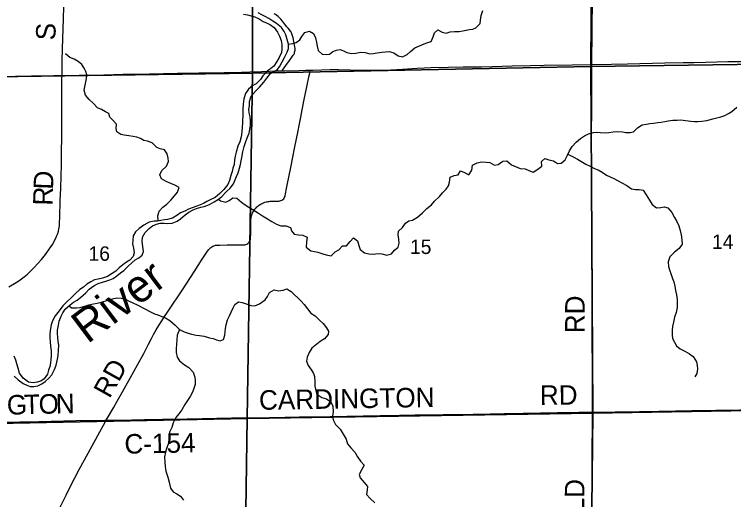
# Model space of a CAD drawing. Extents: x 1584893 to 1934202, y 663575 to 1091909.
# Drawn here: x 1821820 to 1832870, y 914623 to 922073 of the extents above; entities that cross this region are included whole.
import ezdxf

# ---------------------------------------------------------------- set-up
doc = ezdxf.new("R2010")
doc.units = 0
for name, color, linetype in [('GM_X_County_Road', 7, 'Continuous'), ('GM_X_County_Road_Text', 7, 'Continuous'), ('GM_X_Major_River', 7, 'Continuous'), ('GM_X_Major_River_Text', 7, 'Continuous'), ('GM_X_Minor_River', 7, 'Continuous'), ('GM_X_Section', 7, 'Continuous'), ('GM_X_Section_Text', 7, 'Continuous'), ('GM_X_Township_Road', 7, 'Continuous'), ('GM_X_Township_Road_Text', 7, 'Continuous')]:
    doc.layers.add(name, color=color, linetype=linetype)

msp = doc.modelspace()

# ---------------------------------------------------------------- linework, layer by layer
at = {"layer": 'GM_X_County_Road'}
for points in [[(1830693, 921304), (1830693, 921360), (1830695, 921787), (1830698, 921918), (1830701, 922230), (1830703, 922476), (1830705, 922739), (1830708, 923083), (1830710, 923346), (1830712, 923559), (1830715, 923838), (1830718, 924035), (1830719, 924220)], [(1822552, 921136), (1822553, 921203), (1822555, 921351), (1822560, 921548), (1822574, 922007), (1822578, 922188)], [(1830693, 921304), (1830994, 921310), (1831239, 921316), (1831813, 921328), (1832092, 921333), (1832256, 921336), (1832436, 921339), (1832780, 921348), (1832977, 921351), (1833256, 921358), (1833319, 921358)], [(1826362, 921217), (1826405, 921218), (1826667, 921225), (1826798, 921225), (1826978, 921221), (1827142, 921217), (1827323, 921214), (1827437, 921216), (1827601, 921223), (1827781, 921233), (1828010, 921248), (1828223, 921257), (1828485, 921265), (1828715, 921268), (1828994, 921270), (1829158, 921275), (1829469, 921282), (1829748, 921286), (1829961, 921291), (1830387, 921298), (1830682, 921304), (1830693, 921304)], [(1830703, 915967), (1830703, 916109), (1830702, 916322), (1830699, 916700), (1830698, 917028), (1830698, 917159), (1830697, 917373), (1830695, 917816), (1830695, 918013), (1830693, 918292), (1830690, 918833), (1830689, 919211), (1830687, 919473), (1830687, 919769), (1830687, 920277), (1830689, 920589), (1830689, 920819), (1830691, 920999), (1830693, 921304)], [(1818576, 921109), (1818621, 921108), (1818736, 921107), (1818917, 921106), (1819409, 921104), (1819852, 921102), (1820048, 921105), (1820163, 921105), (1820426, 921107), (1820602, 921108), (1820770, 921110), (1820852, 921112), (1821082, 921115), (1821459, 921120), (1821836, 921125), (1822082, 921128), (1822427, 921133), (1822552, 921136)], [(1821735, 917892), (1821849, 917957), (1821890, 917983), (1821931, 918011), (1821970, 918042), (1822020, 918085), (1822124, 918186), (1822180, 918246), (1822234, 918308), (1822296, 918385), (1822345, 918451), (1822382, 918505), (1822385, 918510), (1822408, 918547), (1822432, 918591), (1822454, 918635), (1822474, 918680), (1822485, 918711), (1822495, 918743), (1822503, 918775), (1822511, 918824), (1822515, 918873), (1822519, 918956), (1822525, 919218), (1822531, 919399), (1822538, 919595), (1822543, 919759), (1822546, 919956), (1822548, 920186), (1822548, 920383), (1822548, 920564), (1822549, 920662), (1822551, 920892), (1822551, 921089), (1822552, 921136)], [(1822552, 921136), (1822619, 921137), (1822815, 921139), (1823192, 921147), (1823487, 921154), (1823897, 921162), (1824110, 921166), (1824324, 921169), (1824651, 921176), (1825045, 921182), (1825307, 921188), (1825438, 921192), (1825618, 921198), (1825864, 921204), (1825929, 921205)], [(1823231, 915840), (1823261, 915892), (1823342, 916034), (1823398, 916134), (1823479, 916277), (1823657, 916590), (1823713, 916692), (1823806, 916865), (1823882, 917011), (1823926, 917099), (1823957, 917157), (1823997, 917227), (1824040, 917298), (1824084, 917367), (1824128, 917436), (1824183, 917517), (1824266, 917640), (1824320, 917722), (1824401, 917845), (1824580, 918120), (1824706, 918313), (1824788, 918436), (1824807, 918462), (1824817, 918474), (1824828, 918485), (1824840, 918496), (1824853, 918505), (1824867, 918513), (1824882, 918519), (1824897, 918524), (1824912, 918527), (1824928, 918530), (1824944, 918531), (1824977, 918532), (1825091, 918535), (1825206, 918536), (1825305, 918537), (1825349, 918536), (1825362, 918537), (1825375, 918540), (1825389, 918545), (1825404, 918554), (1825417, 918565), (1825427, 918578), (1825436, 918592), (1825441, 918606), (1825445, 918621), (1825448, 918638), (1825449, 918655), (1825450, 918676), (1825452, 918714), (1825452, 918751), (1825450, 918835), (1825450, 918884), (1825451, 918917), (1825452, 918933), (1825455, 918949), (1825458, 918965), (1825462, 918980), (1825467, 918996), (1825473, 919011), (1825480, 919025), (1825488, 919039), (1825496, 919053), (1825505, 919067), (1825514, 919080), (1825524, 919093), (1825535, 919105), (1825546, 919116), (1825558, 919127), (1825571, 919137), (1825584, 919147), (1825597, 919156), (1825611, 919164), (1825626, 919171), (1825640, 919178), (1825655, 919184), (1825670, 919189), (1825686, 919194), (1825702, 919197), (1825718, 919200), (1825734, 919202), (1825750, 919204), (1825782, 919205), (1825865, 919206), (1825881, 919207), (1825898, 919209), (1825914, 919214), (1825930, 919220), (1825946, 919230), (1825959, 919243), (1825967, 919256), (1825974, 919271), (1825979, 919288), (1825986, 919320), (1826002, 919401), (1826012, 919449), (1826066, 919723), (1826099, 919883), (1826125, 920012), (1826180, 920285), (1826196, 920365), (1826221, 920494), (1826243, 920607), (1826274, 920767), (1826315, 920960), (1826351, 921137), (1826357, 921169), (1826359, 921186), (1826362, 921217)], [(1825929, 921205), (1825979, 921206), (1826192, 921213), (1826290, 921216), (1826362, 921217)], [(1823231, 915840), (1823310, 915842), (1823424, 915843), (1823818, 915851), (1824096, 915856), (1824244, 915859), (1824473, 915864), (1824703, 915867), (1824932, 915872), (1825162, 915876), (1825441, 915880), (1825736, 915884), (1825982, 915890), (1826195, 915894), (1826670, 915901), (1827179, 915909), (1827441, 915913), (1827736, 915919), (1827769, 915920), (1827818, 915921), (1827974, 915923), (1828164, 915925), (1828304, 915926), (1828408, 915928), (1828588, 915931), (1828867, 915936), (1829129, 915941), (1829343, 915944), (1829638, 915950), (1830162, 915959), (1830490, 915963), (1830703, 915967)], [(1830640, 910601), (1830643, 910957), (1830649, 911269), (1830656, 911597), (1830661, 911843), (1830668, 912319), (1830674, 912598), (1830678, 912877), (1830684, 913188), (1830686, 913481), (1830687, 913631), (1830690, 913894), (1830694, 914255), (1830695, 914649), (1830695, 914829), (1830697, 915059), (1830698, 915453), (1830700, 915683), (1830703, 915967)], [(1830703, 915967), (1831048, 915971), (1831425, 915978), (1831720, 915983), (1832228, 915991), (1832966, 916002), (1833245, 916006), (1833318, 916007)], [(1821851, 913136), (1821871, 913176), (1821979, 913397), (1822095, 913634), (1822168, 913780), (1822260, 913973), (1822304, 914061), (1822411, 914281), (1822541, 914547), (1822614, 914693), (1822673, 914811), (1822748, 914956), (1822817, 915087), (1822895, 915231), (1823100, 915606), (1823220, 915820), (1823231, 915840)]]:
    msp.add_lwpolyline(points, dxfattribs=at)
at = {"layer": 'GM_X_Major_River'}
for points in [[(1823171, 917960), (1823227, 917978), (1823285, 917995), (1823339, 918018), (1823394, 918059), (1823449, 918107), (1823499, 918142), (1823570, 918207), (1823625, 918258), (1823675, 918302), (1823730, 918337), (1823782, 918378), (1823801, 918432), (1823783, 918588), (1823788, 918652), (1823827, 918722), (1823892, 918787), (1823943, 918826), (1824001, 918853), (1824057, 918865), (1824119, 918868), (1824177, 918863), (1824245, 918866), (1824320, 918899), (1824372, 918934), (1824445, 918993), (1824500, 919035), (1824566, 919074), (1824618, 919095), (1824685, 919112), (1824735, 919123), (1824815, 919152), (1824888, 919193), (1824954, 919236), (1825005, 919278), (1825072, 919349), (1825135, 919404), (1825186, 919471), (1825206, 919525), (1825233, 919585), (1825256, 919640), (1825279, 919710), (1825294, 919768), (1825305, 919822), (1825313, 919876), (1825329, 919964), (1825348, 920043), (1825371, 920107), (1825398, 920177), (1825425, 920250), (1825438, 920310), (1825448, 920368), (1825449, 920446), (1825440, 920498), (1825425, 920561), (1825422, 920615), (1825433, 920668), (1825433, 920733), (1825454, 920802), (1825487, 920854), (1825532, 920905), (1825583, 920955), (1825654, 921032), (1825696, 921093), (1825757, 921164), (1825810, 921198), (1825860, 921225), (1825897, 921278), (1825932, 921344), (1825969, 921411), (1826010, 921493), (1826031, 921547), (1826030, 921617), (1825988, 921757), (1825965, 921808), (1825921, 921872), (1825846, 921935), (1825791, 921968), (1825727, 922009), (1825674, 922040), (1825620, 922067), (1825563, 922095)], [(1825339, 922078), (1825401, 922064), (1825457, 922050), (1825513, 922034), (1825581, 922005), (1825643, 921965), (1825701, 921939), (1825757, 921915), (1825809, 921874), (1825862, 921802), (1825894, 921740), (1825918, 921670), (1825928, 921610), (1825929, 921544), (1825921, 921486), (1825889, 921412), (1825853, 921348), (1825806, 921278), (1825756, 921238), (1825706, 921207), (1825638, 921127), (1825601, 921071), (1825533, 921007), (1825483, 920979), (1825415, 920925), (1825370, 920858), (1825344, 920774), (1825334, 920696), (1825331, 920618), (1825331, 920556), (1825325, 920406), (1825320, 920336), (1825314, 920270), (1825302, 920192), (1825281, 920114), (1825255, 920050), (1825229, 919958), (1825213, 919894), (1825202, 919840), (1825194, 919768), (1825178, 919714), (1825164, 919660), (1825147, 919598), (1825123, 919522), (1825101, 919462), (1825036, 919386), (1824976, 919322), (1824906, 919263), (1824828, 919227), (1824778, 919201), (1824723, 919171), (1824673, 919149), (1824621, 919128), (1824549, 919102), (1824493, 919082), (1824439, 919054), (1824373, 919025), (1824318, 918987), (1824248, 918943), (1824174, 918923), (1824124, 918919), (1824072, 918908), (1824018, 918900), (1823966, 918898), (1823892, 918882), (1823809, 918839), (1823737, 918783), (1823679, 918735), (1823647, 918673), (1823638, 918603), (1823636, 918551), (1823648, 918481)], [(1823648, 918481), (1823660, 918413), (1823647, 918353), (1823591, 918299), (1823541, 918267), (1823487, 918230), (1823431, 918182), (1823376, 918130), (1823322, 918092), (1823252, 918048), (1823174, 918023), (1823106, 918009), (1823052, 917995), (1822992, 917969), (1822935, 917930), (1822881, 917884), (1822825, 917850), (1822753, 917784), (1822566, 917599), (1822507, 917523), (1822445, 917443), (1822405, 917367), (1822385, 917307), (1822372, 917249), (1822366, 917171), (1822366, 917107), (1822370, 917045), (1822377, 916979), (1822385, 916907), (1822387, 916831), (1822382, 916775), (1822372, 916721), (1822362, 916665), (1822346, 916609), (1822326, 916549), (1822279, 916477), (1822225, 916440), (1822171, 916424), (1822109, 916414), (1822037, 916428), (1821955, 916485), (1821897, 916563), (1821876, 916641), (1821856, 916709), (1821842, 916765), (1821814, 916823)], [(1821816, 916520), (1821879, 916461), (1821957, 916404), (1822010, 916378), (1822062, 916361), (1822118, 916360), (1822182, 916371), (1822239, 916398), (1822295, 916436), (1822348, 916487), (1822393, 916540), (1822436, 916618), (1822463, 916685), (1822484, 916779), (1822491, 916835), (1822498, 916915), (1822501, 916989), (1822494, 917053), (1822487, 917113), (1822481, 917173), (1822482, 917223), (1822497, 917303), (1822510, 917361), (1822537, 917439), (1822562, 917490), (1822601, 917546), (1822676, 917615), (1822730, 917654), (1822785, 917685), (1822841, 917729), (1822910, 917792), (1822971, 917855), (1823040, 917906), (1823108, 917939), (1823171, 917960)]]:
    msp.add_lwpolyline(points, dxfattribs=at)
at = {"layer": 'GM_X_Minor_River'}
for points in [[(1826030, 921617), (1826098, 921626), (1826150, 921641), (1826203, 921680), (1826235, 921732), (1826284, 921793), (1826355, 921816), (1826414, 921782), (1826445, 921715), (1826462, 921639), (1826473, 921583), (1826487, 921520), (1826548, 921464), (1826610, 921455), (1826660, 921464), (1826714, 921501), (1826769, 921523), (1826823, 921534), (1826874, 921513), (1826928, 921488), (1827000, 921473), (1827064, 921480), (1827138, 921491), (1827208, 921490), (1827282, 921467), (1827334, 921473), (1827392, 921482), (1827464, 921493), (1827520, 921500), (1827580, 921503), (1827650, 921484), (1827717, 921435), (1827785, 921422), (1827854, 921458), (1827906, 921505), (1827973, 921558), (1828042, 921591), (1828116, 921620), (1828170, 921639), (1828222, 921655), (1828253, 921726), (1828272, 921790), (1828325, 921837), (1828390, 921798), (1828452, 921785), (1828517, 921805), (1828581, 921810), (1828653, 921809), (1828711, 921818), (1828811, 921841), (1828861, 921848), (1828911, 921865), (1828974, 921932), (1828983, 921986), (1828990, 922054), (1829019, 922132)], [(1824030, 918902), (1824024, 918980), (1824044, 919050), (1824099, 919114), (1824163, 919159), (1824221, 919223), (1824282, 919289), (1824328, 919343), (1824350, 919413), (1824284, 919453), (1824222, 919477), (1824154, 919506), (1824082, 919548), (1824055, 919608), (1824087, 919674), (1824159, 919740), (1824188, 919814), (1824182, 919866), (1824168, 919932), (1824128, 919994), (1824058, 920010), (1824006, 920030), (1823938, 920099), (1823866, 920125), (1823807, 920139), (1823755, 920166), (1823703, 920190), (1823645, 920196), (1823579, 920206), (1823507, 920219), (1823455, 920229), (1823393, 920271), (1823385, 920321), (1823387, 920385), (1823339, 920443), (1823288, 920496), (1823272, 920552), (1823220, 920578), (1823158, 920612), (1823098, 920640), (1823034, 920705), (1822970, 920765), (1822911, 920835), (1822893, 920911), (1822903, 920963), (1822919, 921039), (1822928, 921091), (1822932, 921147), (1822918, 921197), (1822892, 921247), (1822854, 921306), (1822800, 921350), (1822737, 921384), (1822671, 921412), (1822603, 921465)], [(1829456, 919765), (1829592, 919706), (1829668, 919701), (1829722, 919677), (1829790, 919648), (1829862, 919697), (1829923, 919742), (1829918, 919816), (1829969, 919860), (1830033, 919841), (1830101, 919826), (1830166, 919781), (1830220, 919788), (1830281, 919841), (1830316, 919911), (1830347, 919977), (1830388, 920042), (1830451, 920109), (1830518, 920169), (1830581, 920206), (1830641, 920237), (1830717, 920260), (1830768, 920265), (1830826, 920261), (1830898, 920252), (1830950, 920257), (1831018, 920268), (1831086, 920277), (1831162, 920272), (1831216, 920257), (1831278, 920257), (1831333, 920268), (1831394, 920329), (1831464, 920378), (1831531, 920389), (1831581, 920397), (1831639, 920404), (1831705, 920413), (1831757, 920420), (1831812, 920428), (1831866, 920439), (1831936, 920448), (1832002, 920451), (1832058, 920452), (1832128, 920445), (1832212, 920434), (1832264, 920428), (1832322, 920429), (1832383, 920434), (1832457, 920445), (1832549, 920468), (1832674, 920502), (1832736, 920521), (1832789, 920549), (1832841, 920584), (1832920, 920649)], [(1830323, 919925), (1830404, 919888), (1830470, 919851), (1830521, 919820), (1830601, 919775), (1830666, 919742), (1830730, 919709), (1830788, 919686), (1830849, 919649), (1830917, 919606), (1830975, 919580), (1831028, 919553), (1831096, 919516), (1831154, 919489), (1831229, 919446), (1831301, 919397), (1831363, 919384), (1831417, 919385), (1831479, 919373), (1831526, 919304), (1831579, 919219), (1831618, 919154), (1831683, 919103), (1831752, 919108), (1831804, 919118), (1831860, 919101), (1831919, 919030), (1831962, 918955), (1831995, 918893), (1832028, 918824), (1832047, 918756), (1832062, 918688), (1832075, 918611), (1832077, 918547), (1832034, 918478), (1831961, 918423), (1831888, 918349), (1831862, 918274), (1831870, 918204), (1831885, 918149), (1831912, 918077), (1831931, 918020), (1831950, 917966), (1831968, 917900), (1831979, 917832), (1831992, 917765), (1832001, 917697), (1832004, 917643), (1832001, 917573), (1831986, 917495), (1831961, 917423), (1831948, 917345), (1831933, 917279), (1831926, 917223), (1831923, 917151), (1831931, 917099), (1831960, 917041), (1831993, 916986), (1832047, 916937), (1832118, 916904), (1832194, 916861), (1832249, 916818), (1832298, 916740), (1832312, 916683), (1832313, 916631), (1832302, 916561), (1832275, 916508)], [(1824954, 919236), (1824984, 919210), (1825066, 919191), (1825122, 919216), (1825177, 919257), (1825235, 919249), (1825308, 919191), (1825363, 919151), (1825423, 919112), (1825496, 919067), (1825571, 919022), (1825633, 918981), (1825710, 918934), (1825776, 918893), (1825847, 918850), (1825915, 918825), (1825991, 918824), (1826060, 918801), (1826078, 918751), (1826119, 918700), (1826185, 918687), (1826251, 918682), (1826318, 918651), (1826307, 918583), (1826302, 918499), (1826375, 918440), (1826429, 918430), (1826483, 918423), (1826559, 918398), (1826610, 918379), (1826686, 918368), (1826747, 918425), (1826804, 918458), (1826860, 918520), (1826924, 918517), (1826977, 918586), (1827030, 918641), (1827093, 918595), (1827111, 918526), (1827134, 918464), (1827201, 918413), (1827267, 918396), (1827337, 918393), (1827409, 918404), (1827465, 918397), (1827540, 918376), (1827615, 918397), (1827661, 918453), (1827714, 918498), (1827731, 918562), (1827726, 918622), (1827715, 918688), (1827720, 918742), (1827780, 918799), (1827829, 918865), (1827882, 918902), (1827936, 918913), (1828011, 918958), (1828088, 919025), (1828154, 919092), (1828227, 919151), (1828276, 919203), (1828349, 919278), (1828396, 919331), (1828455, 919388), (1828491, 919442), (1828506, 919496), (1828517, 919575), (1828578, 919601), (1828638, 919610), (1828675, 919671), (1828736, 919644), (1828802, 919612), (1828849, 919679), (1828856, 919759), (1828928, 919794), (1829002, 919807), (1829066, 919806), (1829126, 919799), (1829198, 919756), (1829250, 919769), (1829323, 919818), (1829385, 919822), (1829456, 919765)], [(1822659, 917599), (1822699, 917569), (1822773, 917566), (1822829, 917575), (1822915, 917596), (1822966, 917611), (1823036, 917630), (1823092, 917641), (1823174, 917660), (1823239, 917681), (1823329, 917708), (1823393, 917721), (1823461, 917718), (1823525, 917699), (1823584, 917668), (1823638, 917646), (1823708, 917611), (1823823, 917551), (1823910, 917508), (1823970, 917477), (1824025, 917458), (1824083, 917435), (1824143, 917413), (1824210, 917372), (1824289, 917299), (1824358, 917236), (1824430, 917199), (1824488, 917178), (1824543, 917163), (1824611, 917150), (1824665, 917143), (1824737, 917130), (1824815, 917109), (1824872, 917094), (1824924, 917078), (1824982, 917063), (1825034, 917080), (1825053, 917146), (1825056, 917200), (1825063, 917252), (1825073, 917306), (1825096, 917383), (1825125, 917445), (1825152, 917503), (1825179, 917566), (1825208, 917618), (1825262, 917657), (1825318, 917649), (1825380, 917630), (1825454, 917601), (1825515, 917598), (1825586, 917631), (1825673, 917690), (1825706, 917743), (1825740, 917803), (1825809, 917846), (1825877, 917827), (1825947, 917840), (1826003, 917859), (1826073, 917816), (1826124, 917768), (1826175, 917723), (1826224, 917670), (1826274, 917619), (1826321, 917553), (1826376, 917484), (1826443, 917443), (1826508, 917380), (1826562, 917329), (1826615, 917260), (1826646, 917210), (1826643, 917156), (1826586, 917093), (1826516, 917048), (1826443, 916991), (1826392, 916947), (1826347, 916882), (1826316, 916812), (1826310, 916750), (1826331, 916680), (1826386, 916611), (1826417, 916561), (1826432, 916511), (1826437, 916433), (1826436, 916366), (1826449, 916296), (1826468, 916244), (1826542, 916193), (1826613, 916170), (1826679, 916125), (1826714, 916057), (1826717, 915972), (1826708, 915905), (1826719, 915850), (1826754, 915776), (1826827, 915705), (1826872, 915626), (1826915, 915552), (1826940, 915481), (1826987, 915416), (1827050, 915350)], [(1824358, 917236), (1824321, 917150), (1824316, 917076), (1824309, 917016), (1824304, 916934), (1824303, 916882), (1824320, 916810), (1824358, 916753), (1824433, 916694), (1824498, 916649), (1824567, 916578), (1824590, 916504), (1824599, 916454), (1824599, 916392), (1824573, 916314), (1824549, 916260), (1824520, 916207), (1824477, 916143), (1824436, 916082), (1824391, 916003), (1824346, 915941), (1824301, 915884), (1824258, 915800), (1824241, 915732), (1824204, 915659), (1824203, 915605), (1824209, 915543), (1824180, 915475), (1824155, 915407), (1824140, 915350), (1824127, 915278), (1824130, 915200), (1824137, 915130), (1824146, 915057), (1824175, 914969), (1824199, 914891), (1824220, 914796), (1824259, 914742), (1824313, 914713), (1824370, 914674), (1824416, 914615)], [(1827050, 915350), (1827091, 915279), (1827138, 915214), (1827193, 915151), (1827156, 915086), (1827119, 915008), (1827132, 914956), (1827191, 914887), (1827243, 914823), (1827240, 914771), (1827229, 914701), (1827288, 914640), (1827357, 914575)]]:
    msp.add_lwpolyline(points, dxfattribs=at)
at = {"layer": 'GM_X_Section'}
for points in [[(1830712, 926605), (1835981, 926664), (1835926, 921347), (1830676, 921275)], [(1820102, 926457), (1825484, 926537), (1825478, 921170), (1820063, 921092)], [(1825484, 926537), (1830712, 926605), (1830676, 921275), (1825478, 921170)], [(1830676, 921275), (1835926, 921347), (1835852, 916035), (1830705, 915949)], [(1825478, 921170), (1830676, 921275), (1830705, 915949), (1825397, 915868)], [(1820063, 921092), (1825478, 921170), (1825397, 915868), (1819999, 915761)], [(1830705, 915949), (1835852, 916035), (1835759, 910700), (1830648, 910596)], [(1825397, 915868), (1830705, 915949), (1830648, 910596), (1825317, 910550)], [(1819999, 915761), (1825397, 915868), (1825317, 910550), (1819899, 910496)]]:
    msp.add_lwpolyline(points, close=True, dxfattribs=at)
at = {"layer": 'GM_X_Township_Road'}
for points in [[(1825929, 921205), (1825939, 921219), (1825989, 921287), (1826045, 921365), (1826081, 921414), (1826104, 921445), (1826112, 921458), (1826117, 921467), (1826121, 921475), (1826125, 921491), (1826130, 921508), (1826133, 921523), (1826133, 921541), (1826132, 921556), (1826129, 921574), (1826113, 921655), (1826101, 921711), (1826093, 921742), (1826083, 921774), (1826076, 921792), (1826069, 921808), (1826048, 921836), (1826024, 921863), (1826007, 921884), (1825972, 921927), (1825939, 921968), (1825911, 922001), (1825890, 922025), (1825873, 922041), (1825854, 922055), (1825833, 922070), (1825810, 922084)], [(1821656, 915810), (1821902, 915817), (1822197, 915824), (1822770, 915835), (1823207, 915840), (1823231, 915840)]]:
    msp.add_lwpolyline(points, dxfattribs=at)

# ---------------------------------------------------------------- texts
at = {"layer": 'GM_X_County_Road_Text'}
for s, rotation, p in [('S', 88.7506, (1822450, 921672)), ('D', 87.9049, (1822413, 919379)), ('R', 88.3761, (1822406, 919134)), ('RD', 90, (1830581, 917177)), ('RD', 60.8511, (1823283, 916164)), ('RD', 0.489, (1829894, 916076)), ('CARDINGTON', 0.9339, (1825580, 916001)), ('C-154', 1.1031, (1823513, 915327)), ('WESTFIELD', 89.5175, (1830559, 912642))]:
    msp.add_text(s, height=300, rotation=rotation, dxfattribs=at).set_placement(p)
at = {"layer": 'GM_X_Major_River_Text'}
msp.add_text('River', height=500.1, rotation=37.0092, dxfattribs=at).set_placement((1822943, 917005))
at = {"layer": 'GM_X_Section_Text'}
for s, p in [('14', (1832538, 918472)), ('15', (1827898, 918394)), ('16', (1822959, 918290))]:
    msp.add_text(s, height=221, rotation=0, dxfattribs=at).set_placement(p)
at = {"layer": 'GM_X_Township_Road_Text'}
for s, rotation, p in [('G', 1.3539, (1821707, 915926)), ('T', 1.3501, (1821971, 915933)), ('O', 1.3502, (1822195, 915938)), ('N', 1.3539, (1822459, 915944))]:
    msp.add_text(s, height=300, rotation=rotation, dxfattribs=at).set_placement(p)

doc.saveas('drawing.dxf')
